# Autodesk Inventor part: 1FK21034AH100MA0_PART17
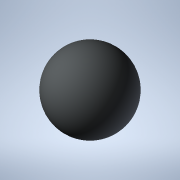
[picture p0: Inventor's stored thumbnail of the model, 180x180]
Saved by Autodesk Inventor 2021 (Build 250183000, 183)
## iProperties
Created: 2025-04
Part Number: 1FK21034AH100MA0_PART17
Material: Generic
Catalog Web Link: www.3dfindit.com
Description: -Servo synchronous motor
Document SubType Name: Modeling
Designer: psAdmin
Mass: 0.113097 g
Surface Area: 1.13097 cm^2
Volume: 0.113097 cm^3
Density: 1 g/cm^3
Appearance: PSOLRGB-212-217-219
Category: PARTsolutions
Title: 1FK21034AH100MA0_PART17
Author: Cadenas PARTsolutions
Comments: Servo synchronous motor
Sending System: PARTsolutions
Preprocessor: ST-DEVELOPER v19.3
PSOL_IDENT_0: {$CADENAS_DATA/23d-libs/siemens_ag/_cat_/39/97/1fk21034ah100ma0.prj},216 {VTYP=3D},{NB=1FK21034AH100
PSOL_IDENT_1: MA0_PART17},{LINA=1FK21034AH100MA0_PART17},{NN=1FK21034AH100MA0_PART17},{NOPRJ=TRUE},{DATE=19.08.202
PSOL_IDENT_2: 5 14:00:33},{GEOMDATE=30.07.2025 02:02:21},{VERSION=},{LINEID=10},{WBVAR=},{WBNUMERIC=}  {NB=1FK2103
PSOL_IDENT_3: 4AH100MA0_PART17},{LINA=1FK21034AH100MA0_PART17},{KT=DUMMY},{PREVIEW=../../../_pool_/d3/78/p_d211_xx
PSOL_IDENT_4: _00934j.png},{DESCSHORT=SIMOTICS S-1FK2 HD, SINAMICS S210 3AC 400V-480V, 1.01 Nm, 4500 rpm},{DESCLON
PSOL_IDENT_5: G=SIMOTICS S-1FK2 HD servo motor M0=1.27 Nm; PN = 0.48 kW at nN=4500 rpm (380-480 V); PN = 0.3 kW at
PSOL_IDENT_6: nN=2500 rpm (200-240 V); with holding brake; degree of protection IP64; cylindrical shaft D14 x 30
PSOL_IDENT_7: mm; absolute encoder 22-bit + 12-bit multiturn (encoder AM22DQC); with OCC interface; plug size M17,
PSOL_IDENT_8: rotatable; SIMOTICS S-1FK2 servomotorfor a wide range of uses in industrial environments. SIMOTICS
PSOL_IDENT_9: S‑1FK2 servomotors are compact synchronous motors with a high dynamic performance that set themselve
PSOL_IDENT_10: s apart as a result of their high power density, degree of protection and overload capability. The m
PSOL_IDENT_11: otors are available in two variants: as High Dynamic variant (highest dynamic performance as a resul
PSOL_IDENT_12: t of the low intrinsic moment of inertia for applications demanding a high dynamic performance with
PSOL_IDENT_13: low moved masses) - and as Compact variant (precise and stable closed-loop control for medium up to
PSOL_IDENT_14: large moved masses as a result of a medium intrinsic moment of inertia). SIMOTICSS‑1FK2 servomotors
PSOL_IDENT_15: fully exploit their strengths in a system with the SINAMICSS210 frequency converter and simple conne
PSOL_IDENT_16: ction using the one cable connection (OCC). Advantages include the short control and positioning tim
PSOL_IDENT_17: es, fast and precise correction of disturbing quantities as well as stable control with a high dynam
PSOL_IDENT_18: ic performance. The servo motors can be configured to address a wide range of requirements. For exam
PSOL_IDENT_19: ple with and without holding brake, IP64 or IP65 degree of protection, singleturn or multiturn absol
PSOL_IDENT_20: ute encoders - to name just a few. Further, the servomotors are available in different shaft heights
PSOL_IDENT_21: extending from 20 to 100. A shaft sealing ring is available to achieve an IP65 degree of protection
PSOL_IDENT_22: and for subsequent mounting at the motor or as spare part. SIMOTICS - the optimum motor for each an
PSOL_IDENT_23: d every motion control application.},{INTNO=195125454019},{SUPPLIERALTNO=1FK2103-4AH10-0MA0},{MANUID=
PSOL_IDENT_24: 1FK21034AH100MA0},{MANUNAME=Siemens},{MANUTYPEDESC=SYNCHRONOUS MOTOR 1FK2 HD 1,27 NM},{AAU732=SIMOTI
PSOL_IDENT_25: CS},{AAO057=S-1FK2},{AAU734=SIMOTICS S-1FK2 HD servo motor M0=1.27 Nm; PN = 0.48 kW at nN=4500 rpm (
PSOL_IDENT_26: 380-480 V); PN = 0.3 kW at nN=2500 rpm (200-240 V); with holding brake; degree of protection IP64; c
PSOL_IDENT_27: ylindrical shaft D14 x 30 mm; absolute encoder 22-bit + 12-bit multiturn (encoder AM22DQC); with OCC
PSOL_IDENT_28: interface; plug size M17, rotatable;},{AAW338=SYNCHRONOUS MOTOR 1FK2 HD 1,27 NM},{AAO742=SIMOTICS},
PSOL_IDENT_29: {AAO663=4034106444921},{NOCUPEROU=1},{PRICEQUANTITY=1},{QUANTITYMIN=1},{QUANTITYINT=1},{CTN=85015100
PSOL_IDENT_30: },{COO=RO},{AAO676=1FK2103-4AH10-0MA0},{AAO677=Siemens AG},{ORDERUNIT=C62},{CONTENTUNIT=C62}
NB: 1FK21034AH100MA0_PART17
NT: Servo synchronous motor
NBSYN: $MANUID._PART17
LINA: 1FK21034AH100MA0_PART17
CATALOG: SIEMENS
PREVIEW: ../../../_pool_/d3/78/p_d211_xx_00934j.png
DESCSHORT: SIMOTICS S-1FK2 HD, SINAMICS S210 3AC 400V-480V, 1.01 Nm, 4500 rpm
DESCLONG: SIMOTICS S-1FK2 HD servo motor M0=1.27 Nm; PN = 0.48 kW at nN=4500 rpm (380-480 V); PN = 0.3 kW at nN=2500 rpm (200-240 V); with holding brake; degree of protec
INTNO: 195125454019
SUPPLIERALTNO: 1FK2103-4AH10-0MA0
MANUID: 1FK21034AH100MA0
MANUNAME: Siemens
MANUTYPEDESC: SYNCHRONOUS MOTOR 1FK2 HD 1,27 NM
AAU732: SIMOTICS
AAO057: S-1FK2
AAU734: SIMOTICS S-1FK2 HD servo motor M0=1.27 Nm; PN = 0.48 kW at nN=4500 rpm (380-480 V); PN = 0.3 kW at nN=2500 rpm (200-240 V); with holding brake; degree of protec
AAW338: SYNCHRONOUS MOTOR 1FK2 HD 1,27 NM
AAO742: SIMOTICS
AAO663: 4034106444921.0
NOCUPEROU: 1
PRICEQUANTITY: 1
QUANTITYMIN: 1
QUANTITYINT: 1
CTN: 85015100
COO: RO
ARTICLENO: 1FK21034AH100MA0_PART17
BOMINFO: 1FK21034AH100MA0_PART17
CREATOR: CADENAS GmbH
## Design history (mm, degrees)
feature "2025_04_17_15_09_00_0361"
body "Solid1"
